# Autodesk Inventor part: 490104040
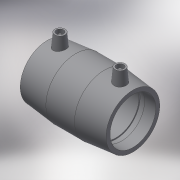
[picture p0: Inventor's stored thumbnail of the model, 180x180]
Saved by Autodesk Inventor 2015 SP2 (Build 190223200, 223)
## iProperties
Created: 2017-06
Part Number: 490104040
Material: Generic
Description: PLASSON COUPLER 40-40
Document SubType Name: Modeling
Designer: KIM
Mass: 106.772 g
Surface Area: 338.545 cm^2
Volume: 106.772 cm^3
Density: 1 g/cm^3
Appearance: Default
Author: KIM
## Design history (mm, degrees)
derived "490104.ipt"
feature "Solid1::490104.ipt"
tag "TaggingFeature1"
body "Solid1"
other parameters: "d0" = 97, "d2" = 56, "d3" = 47, "d4" = 32.33333, "d5" = 50.4, "d6" = 38, "d8" = 168 deg, "d10" = 18.8, "d11" = 6.26667, "d13" = 97, "d14" = 17.6296, "d15" = 47, "d16" = 47, "d17" = 38, "d19" = 3.52592, "d20" = 168 deg, "d22" = 52.64, "d23" = 56, "d24" = 51.0608, "d25" = 135 deg, "d26" = 38.8, "d27" = 135 deg, "d29" = 46, "d30" = 14, "d31" = 33.95, "d34" = 5 deg, "d35" = 15, "d39" = 5 deg, "d41" = 4, "d42" = 14, "d43" = 0, "d45" = 4, "d46" = 14, "d47" = 0, "d48" = 3, "d49" = 0, "d50" = 3, "d51" = 0, "d52" = 13.63, "d53" = 3.4075, "L_" = 97, "L_1" = 47, "D_" = 56, "A_" = 46, "d_2" = 12
